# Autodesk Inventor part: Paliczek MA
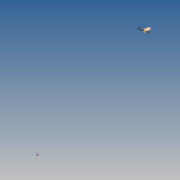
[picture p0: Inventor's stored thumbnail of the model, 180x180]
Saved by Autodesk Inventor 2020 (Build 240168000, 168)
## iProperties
Created: 2019-10
Part Number: Paliczek MA
Material: GFRP
Document SubType Name: Modeling
Designer: yello
Density: 1.75 g/cm^3
Appearance: Default
Author: yello
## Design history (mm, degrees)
feature "Paliczek MA"
sketch "Sketch1"
  geometry: C1 r 2 at (0, 0); 1 further point
  constraints: 1 centre point
  dimensions: "d0" = 4 dimension on point (105.522, -1045.143) C1.centre C1; "d0" = 4 diameter of C1
body "Solid1"
